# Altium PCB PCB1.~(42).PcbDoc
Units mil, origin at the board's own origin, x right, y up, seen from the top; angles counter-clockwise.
Board outline 6000 x 4000 mil, 2 copper layers (Top Layer, Bottom Layer); 37 components, 28 nets, 157 pads, 81 vias.
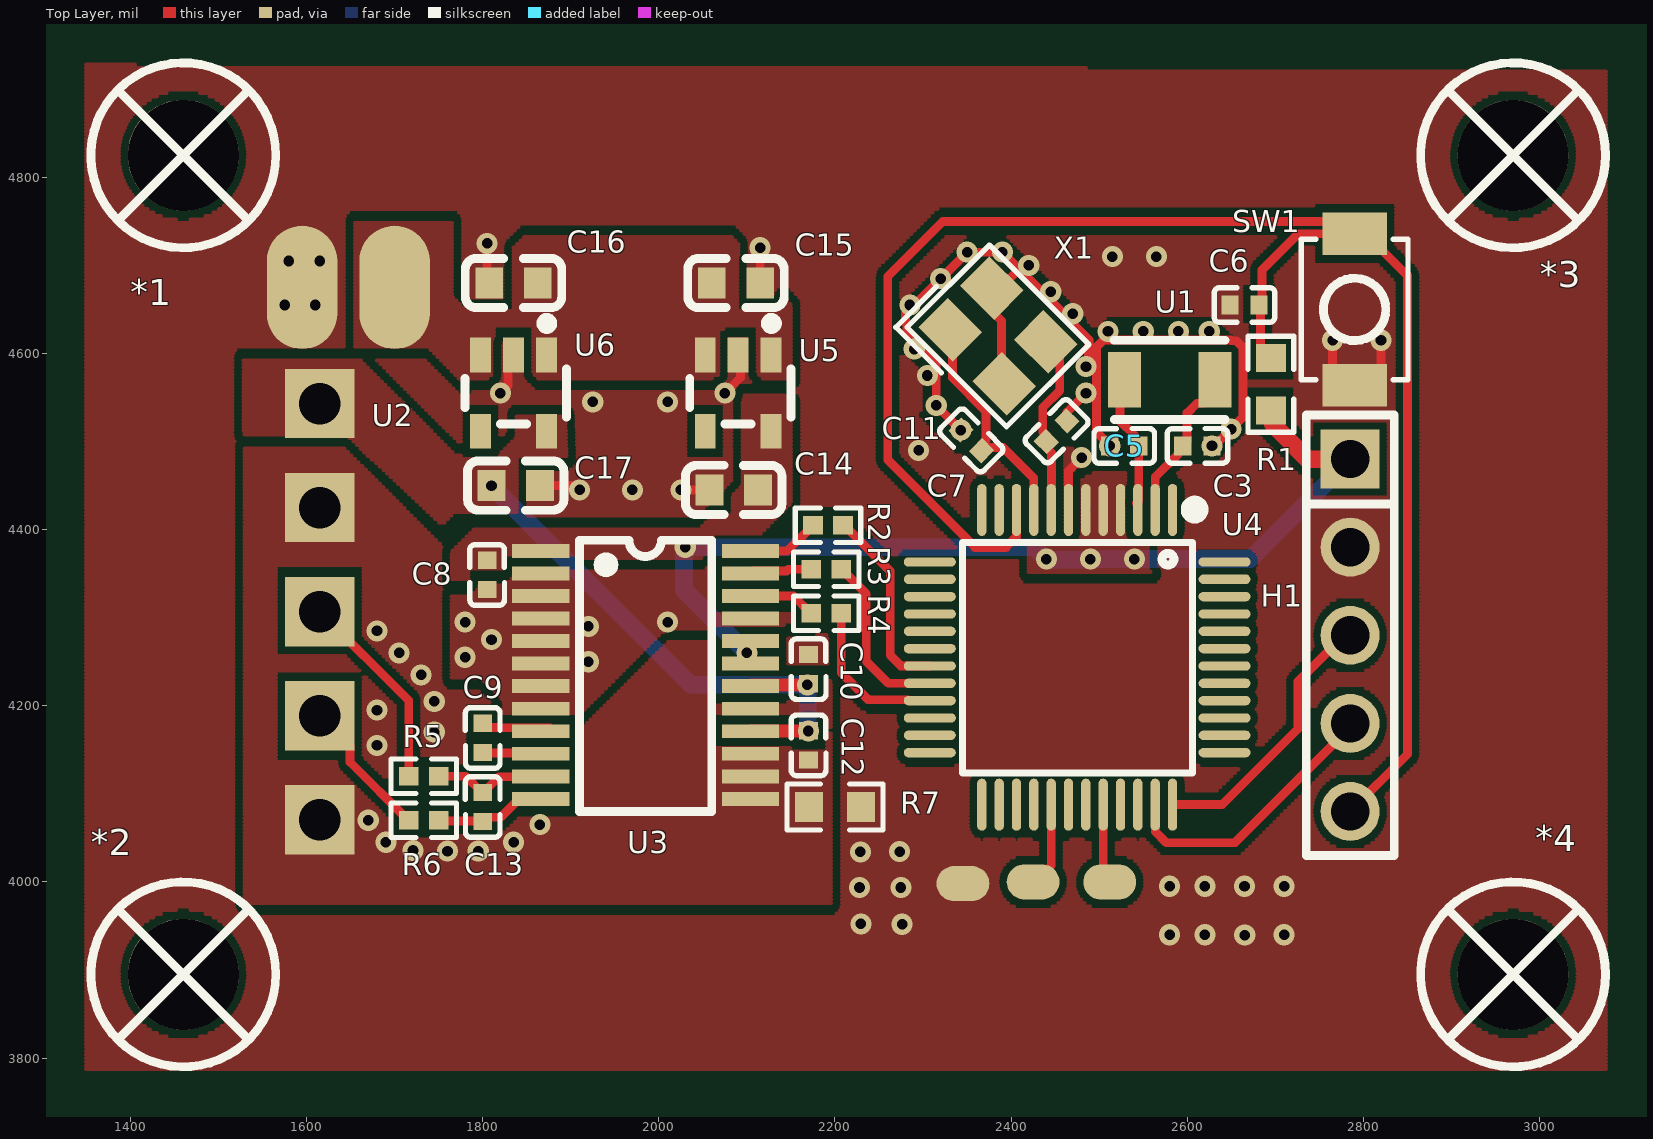
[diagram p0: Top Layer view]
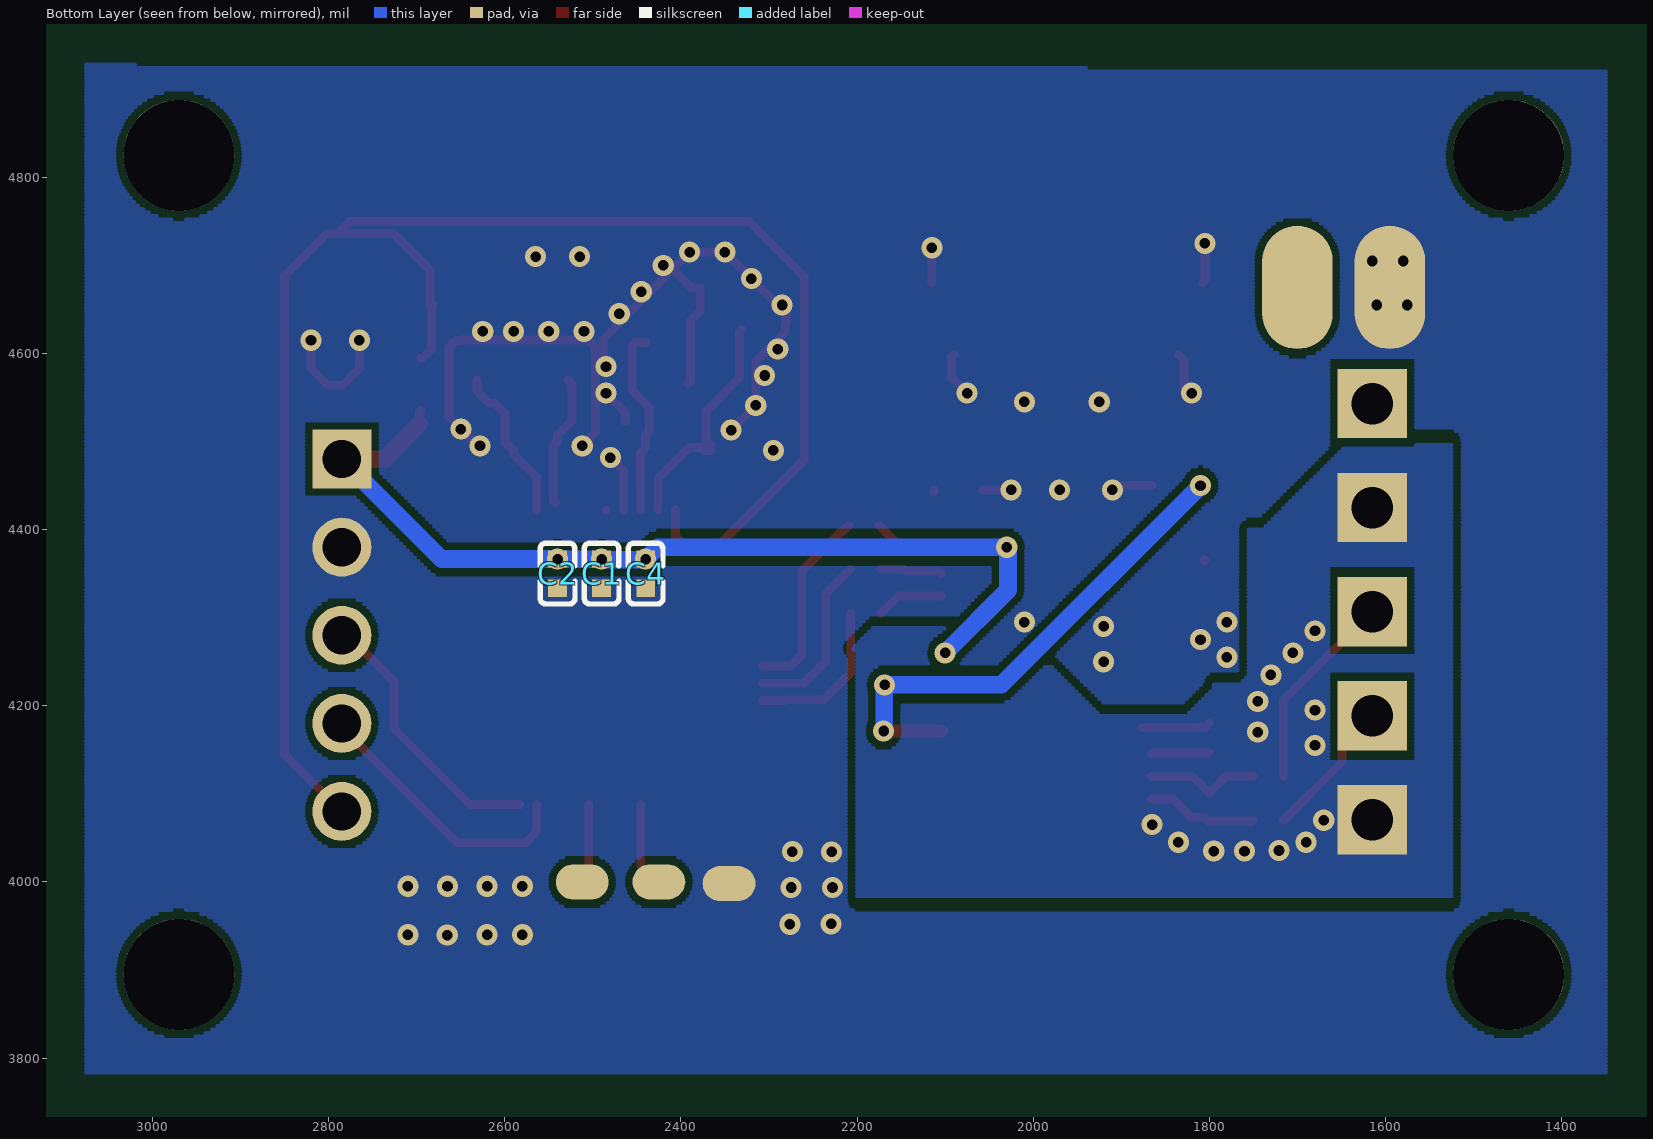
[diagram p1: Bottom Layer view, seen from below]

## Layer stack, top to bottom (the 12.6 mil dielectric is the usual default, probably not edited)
Top Solder: solder mask 0.4, Solder Resist, Dk 3.5
Top Layer: signal copper 1.4
Dielectric 1: dielectric 12.6, FR-4, Dk 4.8
Bottom Layer: signal copper 1.4
Bottom Solder: solder mask 0.4, Solder Resist, Dk 3.5

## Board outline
1000,1000 7000,1000 7000,5000 1000,5000

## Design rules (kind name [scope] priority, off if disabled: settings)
Clearance [All] p1: gap=8 ignorepadtopadclearanceinfootprint=FALSE
ComponentClearance [All] p1: gap=0 collisioncheckmode=3 verticalgap=0 showdistances=FALSE
HoleSize [All] p1: absolutevalues=TRUE maxlimit=130 minlimit=1 maxpercent=80.000 minpercent=20.000
MinimumSolderMaskSliver [All] p1: minsoldermaskwidth=4
PlaneConnect [All] p1: planeconnectstyle=Direct reliefexpansion=20 reliefentries=4 reliefconductorwidth=10 reliefairgap=10
PolygonConnect [All] p1: connectstyle=Direct reliefconductorwidth=10 reliefentries=4 polygonreliefangle="90 Angle" airgapwidth=10
RoutingVias [All] p1: holewidth=28 width=50 viastyle="Through Hole" minholewidth=28 minwidth=50 maxholewidth=28 maxwidth=50
SilkToSilkClearance [All] p1: silktosilkclearance=2
SilkToSolderMaskClearance [IsPad] p1: minsilkscreentomaskgap=2 clearancetoexposedcopper=TRUE
SolderMaskExpansion [All] p1: expansion=0 istentingtop=FALSE
SupplyNets "Schematic Supply Nets_2" [InNet('6V')] p1: voltage=0.000
SupplyNets "Schematic Supply Nets" [InNet('3V3')] p2: voltage=0.000
SupplyNets "Schematic Supply Nets_4" [InNet('5V')] p3: voltage=0.000
SupplyNets "Schematic Supply Nets_3" [InNet('DGND')] p4: voltage=0.000
SupplyNets "Schematic Supply Nets_1" [InNet('AGND')] p5: voltage=0.000
Width [All] p1: maxlimit=50 minlimit=10 preferedwidth=10
24 further rules are at their usual default settings.

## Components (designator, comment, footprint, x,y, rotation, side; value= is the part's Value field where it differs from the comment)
*1 "螺丝孔_1" M3螺丝 1460,4825 r0 top
*2 "螺丝孔_1" M3螺丝 1460,3895 r0 top
*3 "螺丝孔_1" M3螺丝 2970,4825 r0 top
*4 "螺丝孔_1" M3螺丝 2970,3895 r0 top
C1 "cc0402krx7r7bb104" C0402 2490,4350 r90 bottom value=100nF
C2 "cc0402krx7r7bb104" C0402 2540,4350 r270 bottom value=100nF
C3 "cc0402jrnpo9bn220" C0402 2611.54,4495 r180 top value=22pF
C4 "cc0402krx7r7bb104" C0402 2440,4350 r270 bottom value=100nF
C5 "cc0402jrnpo9bn220" C0402 2528.46,4495 r0 top value=22pF
C6 "cc0402krx7r7bb104" C0402 2665,4655 r0 top value=100nF
C7 "cc0402jrnpo9bn180" C0402 2451.7,4511.7 r45 top value=18pF
C8 "cc0402krx7r7bb104" C0402 1805,4348.46 r270 top value=100nF
C9 "cc0402krx7r7bb104" C0402 1800,4163.46 r90 top value=100nF
C10 "cc0402krx7r7bb104" C0402 2170,4241.54 r90 top value=100nF
C11 "cc0402jrnpo9bn180" C0402 2354.68,4501.29 r315 top value=18pF
C12 "gcm155r71h103ka55d" C0402 2170,4155 r270 top value=10nF
C13 "gcm155r71h103ka55d" C0402 1800,4085 r270 top value=10nF
C14 "cga0603x5r105k500jt" C0603 2085,4445 r180 top value=1uF
C15 "cga0603x5r105k500jt" C0603 2087.56,4680 r0 top value=1uF
C16 "cga0603x5r105k500jt" C0603 1835,4680 r180 top value=1uF
C17 "cga0603x5r105k500jt" C0603 1837.44,4450 r0 top value=1uF
H1 "pz254v-11-05p" HDR-TH_5P-P2.54-V-M 2785,4280 r270 top
R1 "frc0603f1002ts" R0603 2695,4565 r270 top value=10kΩ
R2 "frc0402f47r0ts" R0402 2192.04,4405 r0 top value=47Ω
R3 "frc0402f47r0ts" R0402 2190,4355 r0 top value=47Ω
R4 "frc0402f47r0ts" R0402 2190,4305 r0 top value=47Ω
R5 "frc0402f1000ts" R0402 1732.96,4120 r0 top value=100Ω
R6 "frc0402f1000ts" R0402 1732.96,4070 r0 top value=100Ω
R7 "0603waf0000t5e" R0603 2200,4085 r0 top value=0Ω
SW1 "ts-1088-ar02016" SW-SMD_L3.9-W3.0-P4.45 2790,4650 r90 top
U1 "fc31m2-32.768-ntlnndtl" CRYSTAL-SMD_L3.2-W1.5 2580,4570 r0 top value=32.768kHz
U2 "5个焊盘" 5个焊盘 1615,4543.1 r270 top
U3 "ads1232ipwr" TSSOP-24_L7.8-W4.4-P0.65-LS6.4-BL 1985,4235 r270 top
U4 "stm32g031c8t6" LQFP-48_L7.0-W7.0-P0.50-LS9.0-BL 2475,4255 r180 top
U5 "tps7a2033pdbvr" SOT-23-5_L2.9-W1.6-P0.95-LS2.8-BR 2090,4555 r90 top
U6 "tps7a2050pdbvr" SOT-23-5_L2.9-W1.6-P0.95-LS2.8-BR 1835,4555 r90 top
X1 "x32258mob4si" CRYSTAL-SMD_4P-L3.2-W2.5-BL 2385,4620 r315 top value=8MHz

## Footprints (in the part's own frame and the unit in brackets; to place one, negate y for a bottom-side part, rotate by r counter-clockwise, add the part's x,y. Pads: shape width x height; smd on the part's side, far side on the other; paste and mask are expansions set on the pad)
5个焊盘 [mm]
  rect 2x2 hole 1.2: 1(0,0) 2(3,0) 3(6.001,0) 4(9,0) 5(12,0)
C0402 [mm]
  rect 0.5x0.54 smd: 1(-0.42,0) 2(0.42,0)
  silkscreen extent -0.87,-0.5 0.87,0.5
C0603 [mm]
  rect 0.8x0.9 smd: 1(-0.7,0) 2(0.7,0)
  silkscreen extent -1.39,-0.71 1.39,0.71
CRYSTAL-SMD_4P-L3.2-W2.5-BL [mm]
  rect 1.4x1.2 smd: 1(-1.1,-0.85) 2(1.1,-0.85) 3(1.1,0.85) 4(-1.1,0.85)
  silkscreen extent -2.26,-1.91 2.03,1.68
CRYSTAL-SMD_L3.2-W1.5 [mm]
  rect 0.95x1.6 smd: 1(-1.308,0) 2(1.308,0)
  silkscreen extent -1.6,-1.14 1.6,1.14
HDR-TH_5P-P2.54-V-M [mm]
  rect 1.7x1.7 hole 1.1: 1(-5.08,0)
  round 1.7 hole 1.1: 2(-2.54,0) 3(0,0) 4(2.54,0) 5(5.08,0)
  silkscreen extent -6.35,-1.27 6.35,1.27
LQFP-48_L7.0-W7.0-P0.50-LS9.0-BL [mm]
  oval 0.27x1.5 smd paste+0 mask+0.05: 1(-2.75,-4.25) 2(-2.25,-4.25) 3(-1.75,-4.25) 4(-1.25,-4.25) 5(-0.75,-4.25) 6(-0.25,-4.25) 7(0.25,-4.25) 8(0.75,-4.25) 9(1.25,-4.25) 10(1.75,-4.25) 11(2.25,-4.25) 12(2.75,-4.25) 25(2.75,4.25) 26(2.25,4.25) 27(1.75,4.25) 28(1.25,4.25) 29(0.75,4.25) 30(0.25,4.25) 31(-0.25,4.25) 32(-0.75,4.25) 33(-1.25,4.25) 34(-1.75,4.25) 35(-2.25,4.25) 36(-2.75,4.25)
  oval 1.5x0.27 smd paste+0 mask+0.05: 13(4.25,-2.75) 14(4.25,-2.25) 15(4.25,-1.75) 16(4.25,-1.25) 17(4.25,-0.75) 18(4.25,-0.25) 19(4.25,0.25) 20(4.25,0.75) 21(4.25,1.25) 22(4.25,1.75) 23(4.25,2.25) 24(4.25,2.75) 37(-4.25,2.75) 38(-4.25,2.25) 39(-4.25,1.75) 40(-4.25,1.25) 41(-4.25,0.75) 42(-4.25,0.25) 43(-4.25,-0.25) 44(-4.25,-0.75) 45(-4.25,-1.25) 46(-4.25,-1.75) 47(-4.25,-2.25) 48(-4.25,-2.75)
  silkscreen extent -3.59,-4.46 3.3,3.34
M3螺丝 [mil]
  round 126 hole 126 paste-99999 mask+4: 1(0,0)
  silkscreen extent -105,-105 105,105
R0402 [mm]
  rect 0.566x0.54 smd paste-100 mask+0.051: 1(-0.433,0) 2(0.433,0)
  silkscreen extent -0.94,-0.5 0.94,0.5
R0603 [mil]
  rect 31.75x34.02 smd paste-3937.01 mask+2: 1(-29.66,0) 2(29.66,0)
  silkscreen extent -55,-26 55,26
SOT-23-5_L2.9-W1.6-P0.95-LS2.8-BR [mm]
  rect 1x0.6 smd paste+0 mask+0.05: 1(1.1,-0.95) 2(1.1,0) 3(1.1,0.95) 4(-1.1,0.95) 5(-1.1,-0.95)
  silkscreen extent -0.89,-1.52 2.16,1.4
SW-SMD_L3.9-W3.0-P4.45 [mm]
  rect 1.23x1.86 smd: 1(-2.185,0) 2(2.185,0)
  silkscreen extent -2.03,-1.54 2.03,1.54
TSSOP-24_L7.8-W4.4-P0.65-LS6.4-BL [mm]
  rect 0.4x1.65 smd: 1(-3.575,-3.023) 2(-2.925,-3.023) 3(-2.275,-3.023) 4(-1.625,-3.023) 5(-0.975,-3.023) 6(-0.325,-3.023) 7(0.325,-3.023) 8(0.975,-3.023) 9(1.625,-3.023) 10(2.275,-3.023) 11(2.925,-3.023) 12(3.575,-3.023) 13(3.575,3.023) 14(2.925,3.023) 15(2.275,3.023) 16(1.625,3.023) 17(0.975,3.023) 18(0.325,3.023) 19(-0.325,3.023) 20(-0.975,3.023) 21(-1.625,3.023) 22(-2.275,3.023) 23(-2.925,3.023) 24(-3.575,3.023)
  silkscreen extent -3.89,-1.91 3.94,1.91

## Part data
C1 C2 C4 C6 C8 C9 C10: "容值:100nF;精度:±10%;额定电压:16V;温度系数:X7R;", JLCPCB Part Class="Extended Part", LCSC Part Name="100nF ±10% 16V", Manufacturer=YAGEO(国巨), ManufacturerPart=CC0402KRX7R7BB104, Temperature Coefficient=X7R, Tolerance=±10%, Voltage Rating=16V
C3 C5: "容值:22pF;精度:±5%;额定电压:50V;温度系数:NP0;", JLCPCB Part Class="Extended Part", LCSC Part Name="22pF ±5% 50V", Manufacturer=YAGEO(国巨), ManufacturerPart=CC0402JRNPO9BN220, Temperature Coefficient=NP0, Tolerance=±5%, Voltage Rating=50V
C7 C11: "容值:18pF;精度:±5%;额定电压:50V;温度系数:NP0;", JLCPCB Part Class="Extended Part", LCSC Part Name="18pF ±5% 50V", Manufacturer=YAGEO(国巨), ManufacturerPart=CC0402JRNPO9BN180, Temperature Coefficient=NP0, Tolerance=±5%, Voltage Rating=50V
C12 C13: "容值:10nF;精度:±10%;额定电压:50V;温度系数:X7R;", JLCPCB Part Class="Extended Part", LCSC Part Name="10nF ±10% 50V", Manufacturer=muRata(村田), ManufacturerPart=GCM155R71H103KA55D, Temperature Coefficient=X7R, Tolerance=±10%, Voltage Rating=50V
C14 C15 C16 C17: "容值:1uF;精度:±10%;额定电压:50V;温度系数:X5R;", JLCPCB Part Class="Extended Part", LCSC Part Name="1uF ±10% 50V 停产", Manufacturer=HRE(芯声), ManufacturerPart=CGA0603X5R105K500JT, Temperature Coefficient=X5R, Tolerance=±10%, Voltage Rating=50V
H1: "插针结构:1x5P;间距:2.54mm;行距:-;圆针/方针:方针;安装方式:直插;排数:单排;总PIN位数:5P;额定电流:3A;额定电压:250V;配合针长度:6mm;塑高:2.5mm;端接针长度:3mm;触头材质:黄铜;触头镀层:-;工作温度:-40℃~+105℃;颜色:黑色;", Color=黑色, Current Rating=3A, JLCPCB Part Class="Extended Part", LCSC Part Name="1x5P 间距:2.54mm 方针 直插", Manufacturer=XFCN(兴飞), ManufacturerPart=PZ254V-11-05P, Operating Temperature=-40℃~+105℃, Voltage Rating (Max)=250V
R1: "电阻类型:厚膜电阻;阻值:10kΩ;精度:±1%;功率:100mW;工作电压:75V;温度系数:±100ppm/℃;", JLCPCB Part Class="Extended Part", LCSC Part Name="10kΩ ±1% 100mW 厚膜电阻", Manufacturer=FOJAN(富捷), ManufacturerPart=FRC0603F1002TS, Operating Temperature=-55℃~+155℃, Power(Watts)=100mW, Temperature Coefficient=±100ppm/℃, Tolerance=±1%, Voltage-Supply(Max)=75V
R2 R3 R4: "电阻类型:厚膜电阻;阻值:47Ω;精度:±1%;功率:62.5mW;工作电压:50V;温度系数:±100ppm/℃;", JLCPCB Part Class="Extended Part", LCSC Part Name="47Ω ±1% 62.5mW 厚膜电阻", Manufacturer=FOJAN(富捷), ManufacturerPart=FRC0402F47R0TS, Operating Temperature=-55℃~+155℃, Power(Watts)=62.5mW, Temperature Coefficient=±100ppm/℃, Tolerance=±1%, Voltage-Supply(Max)=50V
R5 R6: "电阻类型:厚膜电阻;阻值:100Ω;精度:±1%;功率:62.5mW;工作电压:50V;温度系数:±100ppm/℃;", JLCPCB Part Class="Extended Part", LCSC Part Name="100Ω ±1% 62.5mW 厚膜电阻", Manufacturer=FOJAN(富捷), ManufacturerPart=FRC0402F1000TS, Operating Temperature=-55℃~+155℃, Power(Watts)=62.5mW, Temperature Coefficient=±100ppm/℃, Tolerance=±1%, Voltage-Supply(Max)=50V
R7: "电阻类型:厚膜电阻;阻值:0Ω;精度:±1%;功率:100mW;工作电压:75V;温度系数:-;", JLCPCB Part Class="Basic Part", LCSC Part Name="0Ω ±1% 100mW 厚膜电阻", Manufacturer=UNI-ROYAL(厚声), ManufacturerPart=0603WAF0000T5E, Operating Temperature=-55℃~+155℃, Power(Watts)=100mW, Temperature Coefficient=-, Tolerance=±1%, Voltage-Supply(Max)=75V
SW1: "电路结构:单刀单掷;按钮形状:圆形按钮;作用力:1.6N;安装方式:立贴;开关长度:3.9mm;开关宽度:3mm;开关高度:2mm;带支架:不带支架;触点电流:50mA;额定电压:12V;带灯:-;工作寿命:10万次;", Actuator/Cap Color=黑色, Contact Current=50mA, IP Rating=-, JLCPCB Part Class="Basic Part", LCSC Part Name="3.9*3*2mm 立贴 轻触开关", Manufacturer=XUNPU(讯普), ManufacturerPart=TS-1088-AR02016, Operating Force=1.6N, Operating Temperature=-30℃~+80℃, Voltage Rating=12V
U1: "晶振类型:贴片晶振;频率:32.768kHz;常温频差:±10ppm;负载电容:12.5pF;频率稳定度:±10ppm;", Equivalent Series Resistance(ESR)=70kΩ, Frequency Stability=±10ppm, JLCPCB Part Class="Extended Part", LCSC Part Name="3215 2P 32.768kHz 12.5pF ±10ppm -40~+85℃(±10ppm)", Load Capacitance=12.5pF, Manufacturer=HCI(杭晶), ManufacturerPart=FC31M2-32.768-NTLNNDTL, Operating Temperature=-40℃~+85℃
U3: "分辨率(位):24;采样率:10Hz;工作电压:2.7V~5.3V;接口类型:SPI;", Clock Frequency=4.9152MHz；200kHz~8MHz, JLCPCB Part Class="Extended Part", LCSC Part Name="用于桥式传感器的24bit 模数转换器", Manufacturer=TI(德州仪器), ManufacturerPart=ADS1232IPWR, Operating Temperature=-40℃~+105℃, Quiescent Current (Iq)=1.3uA, Temperature Sensors=内置, Voltage - Supply=2.7V~5.3V, Voltage Reference=外置, Voltage Reference Drift=-
U4: "CPU内核:ARM Cortex-M0+;CPU最大主频:64MHz;CPU位数:32 Bit;", JLCPCB Part Class="Extended Part", LCSC Part Name="主流Arm Cortex-M0+ MCU，具有64 KB Flash存储器、8 KB RAM、64 MHz CPU、2x USART、定时器、ADC和通信接口，1.7-3.6V", Manufacturer=ST(意法半导体), ManufacturerPart=STM32G031C8T6, Operating Temperature=-40℃~+85℃, Voltage - Supply=1.7V~3.6V
U5: "输出类型:固定;最大输入电压:6V;输出电压:3.3V;输出电流:300mA;输出极性:正极;", Dropout Voltage=140mV@(300mA), JLCPCB Part Class="Extended Part", LCSC Part Name="具有高 PSRR 的 300mA、超低噪声、低 IQ、低压降 (LDO) 线性稳压器", Manufacturer=TI(德州仪器), ManufacturerPart=TPS7A2033PDBVR, Maximum Input Voltage=6V, Operating Temperature=-40℃~+125℃@(Tj), Output Current=300mA, Output Voltage=3.3V, standby current=15uA
U6: "输出极性:正极;工作电压:6V;输出电压:5V;输出电流:300mA;电源纹波抑制比(PSRR):65dB@(100Hz);输出类型:固定;", JLCPCB Part Class="Extended Part", LCSC Part Name="800mV~5.5V 300mA 6V", Manufacturer=TI(德州仪器), ManufacturerPart=TPS7A2050PDBVR, Operating Temperature=-40℃~+125℃@(Tj), Output Current=300mA, Output Voltage=5V, Power Supply Rejection Ratio (PSRR)=65dB@(100Hz), standby current=6.5uA, Voltage - Supply=6V, Voltage Dropout=140mV@(300mA)
X1: "晶振类型:贴片晶振;频率:8MHz;常温频差:±10ppm;负载电容:12pF;频率稳定度:±20ppm;", Equivalent Series Resistance(ESR)=180Ω, Frequency Stability=±20ppm, JLCPCB Part Class="Extended Part", LCSC Part Name="YSX321SL 8MHZ 4P 3225 12PF ±10PPM -40~85℃ (±20PPM)", Load Capacitance=12pF, Manufacturer=YXC(扬兴晶振), ManufacturerPart=X32258MOB4SI, Normal temperature Frequency Tolerance=±10ppm, Operating Temperature=-40℃~+85℃

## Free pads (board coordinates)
  oval 80x140 all layers, no hole: 7(1595,4675) 7(1700,4675)
  oval 60x40 all layers, no hole: 7(2345.3,3998) 7(2425,4000) 7(2512,3999.83)

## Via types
v1: diameter 24, hole 12, Top Layer to Bottom Layer, tented both sides, 81 vias

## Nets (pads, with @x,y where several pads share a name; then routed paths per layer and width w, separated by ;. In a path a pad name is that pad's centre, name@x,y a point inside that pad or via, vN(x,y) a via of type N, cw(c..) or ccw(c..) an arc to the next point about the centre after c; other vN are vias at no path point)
3V3: C1.2 C2.1 C4.1 C8.1 C14.1 H1.1 R1.2 U3.1 U3.19 U3.20 U4.4 U4.5 U4.6 U5.5 | length 1084.5
  Top Layer w10: C8.1 C8.1@1805.79,4365 ; C14.1@2112.56,4443.03 C14.1 ; v1(2440,4366.54) v1@2442.68,4369.22 ; U4.6@2484.72,4422.2 U4.6 ; R1.2 2697.01,4533.33 R1.2@2697.01,4519.53
  Top Layer w20: R1.2@2697.01,4519.53 2736.54,4480 H1.1
  Bottom Layer w10: v1@2028.6,4378.6 v1(2030,4380) ; 2058.74,4380 2060.53,4378.21
  Bottom Layer w20: v1@2028.6,4378.6 2028.6,4331.4 v1(2100,4260) ; v1@2030.11,4379.89 2426.18,4379.89 C4.1@2439.37,4366.7 ; C4.1@2440.69,4365.85 C1.2@2489.31,4365.85 ; C1.2@2490.63,4366.49 C2.1@2539.37,4366.49 ; v1(2540,4366.54) 2671.54,4366.54 H1.1
  other v1: 2490,4366.54
5V: C10.1 C12.1 C17.1 U2.1 U3.16 U3.18 U6.5 | length 638.5
  Top Layer w10: U3.16 U3.16@2104.26,4171.28 ; U3.18 U3.18@2105.39,4223.6 ; v1(2168.61,4223.6) C10.1 ; v1(2169.74,4171.28) C12.1
  Top Layer w15: U3.16@2104.26,4171.28 v1(2169.74,4171.28) ; U3.18@2105.39,4223.6 v1(2168.61,4223.6)
  Bottom Layer w10: v1(2168.61,4223.6) v1@2169.17,4223.04 ; v1@2169.17,4171.85 v1(2169.74,4171.28)
  Bottom Layer w20: v1(1810,4450) 2036.39,4223.6 v1(2168.61,4223.6) ; v1@2169.17,4171.85 v1@2169.17,4223.04
6V: C15.1 C16.1 pad.7@1700,4675 U5.1 U5.3 U6.1 U6.3
AGND: C10.2 C12.2 R7.1 U2.2 U2.5 U3.13 U3.14 U3.15 U3.17
  other v1: 1760,4035 1795,4035 1720.87,4035.63 1690,4045 1835,4045 1865,4065 1670,4070 1680,4155 1745,4170 1680,4195 1745,4205 1730,4235 1705,4260 1680,4285
AINN1: R6.1 U2.4 | length 160.9
  Top Layer w10: U2.4 1649.37,4154.39 1649.37,4136.04 1715.41,4070 R6.1
AINP1: R5.1 U2.3 | length 228.7
  Top Layer w10: U2.3 1715.92,4205.94 R5.1
DGND: C1.1 C2.2 C3.1 C4.2 C5.1 C6.1 C7.2 C8.2 C11.1 C14.2 C15.2 C16.2 C17.2 H1.2 pad.7@1595,4675 pad.7@2345.3,3998 R7.2 SW1.1 U3.2 U3.3 U3.4 U3.5 U3.6 U3.7 U3.8 U3.21 U4.7 U5.2 U6.2 X1.2 X1.4 | length 1554.1
  Top Layer w10: v1(1805,4725) 1805,4682.44 C16.2 ; v1(1820,4555) 1828.62,4563.62 1828.62,4591.92 U6.2 ; C17.2 1901.21,4450 1906.21,4445 v1(1910,4445) ; v1(2025,4445) C14.2 ; v1(2075,4555) 2092.68,4572.68 2092.68,4595.63 U5.2 ; v1(2115,4720) 2115.12,4719.88 C15.2 ; v1(2342.98,4512.98) v1(2315,4540.96) 2315,4590.88 2281.52,4624.36 2281.52,4633.48 2280,4635 2280,4645 v1(2350,4715) v1(2390,4715) v1@2409.14,4695.86 ; X1.2 2389.18,4568.5 2389.18,4636.81 2378.04,4647.95 X1.4 2387.57,4674.29 v1@2409.14,4695.86 ; C7.2 2462.83,4523.95 2462.83,4530.8 2463.39,4531.35 2463.39,4533.39 v1(2485,4555) ; U4.7 2465.16,4466.85 v1(2480,4481.69) v1@2480,4485 ; v1(2485,4585) 2487.68,4587.68 2487.68,4604.07 2488.48,4604.87 2488.48,4615.64 2457.06,4647.06 2457.06,4647.94 v1@2409.14,4695.86 ; v1(2511.92,4495) 2511.92,4495.79 2496.8,4510.91 2496.8,4606.88 2505.36,4615.44 2649.41,4615.44 2650.35,4614.5 2655.59,4614.5 2663.2,4606.88 2663.2,4527.61 v1(2649.71,4514.12) 2636.22,4500.63 2632.92,4500.63 C3.1@2628.08,4495.79 ; v1(2765,4615) 2765,4583.19 2784.21,4563.98 SW1.1 2800.79,4563.98 2820,4583.19 v1(2820,4615)
  other v1: 2580,3940 2620,3940 2665.24,3939.54 2710,3940 2229.44,3952.22 2276.16,3951.9 2227.87,3993.61 2274.91,3993.61 2580,3995 2620,3995 2665,3995 2710,3995 2228.81,4034.06 2273.34,4034.38 1920,4250 1780,4255 1810,4275 1920,4290 1780,4295 2010,4295 1970,4445 2295,4490 2628.08,4495 1925,4545 2010,4545 2305,4575 2290,4605 2510,4625 2550,4625 2590,4625 2625,4625 2470,4645 1575,4655 1610,4655 2285,4655 2445,4670 2320,4685 2420,4700 1580,4705 1615,4705 2515,4710 2565,4710
DOUT: R2.2 U4.19 | length 220.8
  Top Layer w10: R2.2 2214.71,4399.37 2216.12,4399.37 2262.67,4352.82 2262.67,4257.23 2274.62,4245.28 2307.56,4245.28 U4.19
NetC3_2: C3.2 U1.2 U4.2 | length 179.8
  Top Layer w10: U4.2 2563.58,4440 2563.58,4459.72 2590.16,4486.3 2590.16,4490.16 2599.84,4499.84 2599.84,4532.3 2611.05,4543.5 2617.8,4543.5 2631.5,4557.21 U1.2
NetC5_2: C5.2 U1.1 U4.3 | length 152
  Top Layer w10: U1.1 2523.5,4565 2523.5,4523.5 2540.16,4506.85 2540.16,4499.84 C5.2 2545,4432.48 U4.3@2542.53,4430
NetC7_1: C7.1 U4.8 X1.3 | length 216.4
  Top Layer w10: X1.3 2440,4612.33 2452.33,4612.33 2455.11,4609.54 2455.11,4557.75 2435.91,4538.56 2435.91,4510.93 2440,4506.85 2440,4493.15 2445.87,4487.28 2445.87,4447.11 2445.59,4446.82 2445.59,4422.89 U4.8@2445.76,4422.72
NetC9_1: C9.1 U3.10 | length 66.6
  Top Layer w10: C9.1 1800.74,4146.18 1865.26,4146.18 U3.10
NetC9_2: C9.2 U3.9 | length 78.3
  Top Layer w10: C9.2 1804.84,4175.16 1819.84,4175.16 1820,4175 U3.9@1876.23,4175
NetC11_2: C11.2 U4.9 X1.1 | length 267.5
  Top Layer w10: X1.1 2333.5,4624.18 2333.5,4572.39 2371.34,4534.54 2371.34,4501.41 2366.37,4496.44 C11.2 2373.22,4489.59 2376.7,4493.07 2391.02,4493.07 2425.67,4458.42 2425.67,4422.44 U4.9
NetC13_1: C13.1 R5.2 U3.11 | length 131.2
  Top Layer w10: R5.2 1780.75,4120 1799.21,4101.54 C13.1 1800.79,4101.54 1818.52,4119.27 1865.43,4119.27 U3.11
NetC13_2: C13.2 R6.2 U3.12 | length 127.3
  Top Layer w10: R6.2 1750.77,4069.23 1799.23,4069.23 C13.2 1804.84,4073.3 1820.44,4073.3 1841.39,4094.26 U3.12
NetR2_1: R2.1 U3.24 | length 83.4
  Top Layer w10: U3.24 2145.74,4375.74 2168.86,4398.86 2168.86,4399.37 2174.49,4405 R2.1
NetR3_1: R3.1 U3.23 | length 71
  Top Layer w10: U3.23 2106.87,4353.02 2144.85,4353.02 2146.82,4355 R3.1
NetR4_1: R4.1 U3.22 | length 77.1
  Top Layer w10: U3.22 2152.89,4324.56 2172.45,4305 R4.1
NRST: C6.2 H1.5 R1.1 SW1.2 U4.10 | length 1937.5
  Top Layer w10: U4.10 2405.98,4422.2 2405.98,4391.77 2394.01,4379.79 2359.14,4379.79 2259.83,4479.1 2259.83,4687.33 2322.36,4749.85 2776.17,4749.85 SW1.2 ; C6.2 C6.2@2681.54,4655.79 ; R1.1 2693.87,4594.66 2682.99,4605.54 2682.99,4652.99 2685,4655 2685,4695 2726.02,4736.02 SW1.2 ; H1.5 2850,4145 2850,4688.42 2802.4,4736.02 SW1.2
PDWN: R4.2 U4.21 | length 181.3
  Top Layer w10: R4.2 2207.04,4237.44 2237.61,4206.87 2282.22,4206.87 2283.3,4205.79 U4.21
SCLK: R3.2 U4.20 | length 199
  Top Layer w10: R3.2 2207.55,4355 2235.58,4326.97 2235.58,4250.61 2260.6,4225.59 2307.56,4225.59 U4.20
SWCLK: H1.3 U4.36 | length 312.7
  Top Layer w10: U4.36 2639.37,4087.68 2725.86,4174.17 2725.86,4227.64 2778.22,4280 H1.3
SWDIO: H1.4 U4.35 | length 315.9
  Top Layer w10: U4.35 2563.7,4087.56 2563.7,4057.14 2576.32,4044.52 2654.07,4044.52 2785,4175.45 H1.4
USART1_RX: pad.7@2512,3999.83 U4.32 | length 90.9
  Top Layer w10: U4.32 2504.65,4087.56 2504.65,4007.18 pad.7@2512,3999.83
USART1_TX: pad.7@2425,4000 U4.29 | length 97.3
  Top Layer w10: pad.7@2425,4000 2426.88,4000 2445.47,4018.59 U4.29
USART2_RX: U4.14
USART2_TX: U4.13
pads on no net: *1.1 *2.1 *3.1 *4.1 U4.1 U4.11 U4.12 U4.15 U4.16 U4.17 U4.18 U4.22 U4.23 U4.24 U4.25 U4.26 U4.27 U4.28 U4.30 U4.31 U4.33 U4.34 U4.37 U4.38 U4.39 U4.40 U4.41 U4.42 U4.43 U4.44 U4.45 U4.46 U4.47 U4.48 U5.4 U6.4

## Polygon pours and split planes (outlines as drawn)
DGND on Top Layer "NONET_L-01_P-001" (hatched Horizontal grid 4 track 5, remove dead copper, pour order 15): 1350,4928.2 1350,3785 3075,3785 3075,4921.81
5V on Top Layer "NONET_L-01_P-001" (hatched Horizontal grid 4 track 5, remove dead copper, pour order 9): 1893.57,4530 1873.57,4530 1838.57,4530 1838.57,4505 1818.57,4485 1768.57,4485 1658.57,4595 1528.57,4595 1528.57,4505 1645,4505 1680,4475 1753.57,4405 1768.57,4420 1838.57,4420 1838.57,4480 1843.57,4485 1848.57,4480 1895,4480
3V3 on Top Layer "NONET_L-01_P-001" (hatched Horizontal grid 4 track 5, remove dead copper, pour order 8): 2420,4385 2420,4350 2560,4350 2555,4355 2555,4385 2545,4385 2535,4395 2535,4465 2475,4465 2475,4390 2425,4390
AGND on Top Layer "NONET_L-01_P-001" (hatched Horizontal grid 4 track 5, remove dead copper, pour order 7): 1565,4495 1640,4495 1755,4380 1755,4225 1795,4225 1827.5,4192.5 1907.5,4192.5 1915,4185 2010,4280 2180,4280 2185,4285 2195,4275 2195,3975 2180,3975 2160,3975 1530,3975 1530,4495
DGND on Top Layer "NONET_L-01_P-001" (hatched Horizontal grid 4 track 5, remove dead copper, pour order 5): 1765,4340 1820,4340 1832.5,4352.5 1830,4355 1830,4365 1905,4365 1960,4310 2135,4310 2135,4290 2130,4285 2005,4285 1905,4185 1830,4185 1830,4200 1800,4230 1765,4230
6V on Top Layer "NONET_L-01_P-001" (hatched Horizontal grid 4 track 5, remove dead copper, pour order 3): 1655,4750 1655,4605 1740,4605 1780,4565 1785,4570 1810,4570 1810,4615 1820,4625 1855,4625 1855,4580 1865,4570 2070,4570 2070,4625 2075,4630 2105,4630 2105,4585 2120,4570 2150,4570 2150,4655 2140,4665 2090,4665 2090,4725 2080,4735 1850,4735 1835,4720 1835,4650 1780,4650 1765,4665 1765,4750
3V3 on Top Layer "NONET_L-01_P-001" (hatched Horizontal grid 4 track 5, remove dead copper, pour order 2): 2095,4555 2095,4450 2045,4400 1790,4400 1765,4375 1765,4340 1820,4340 1845,4365 2045,4365 2070,4390 2110,4390 2150,4430 2150,4545 2140,4555
DGND on Bottom Layer "NONET_L-01_P-001" (hatched Horizontal grid 4 track 5, remove dead copper, pour order 16): 3075,4928.2 3075,3780 1350,3780 1350,4921.81
AGND on Bottom Layer "NONET_L-01_P-001" (hatched Horizontal grid 4 track 5, remove dead copper, pour order 12): 1525,4500 1640,4500 1740,4400 1755,4400 1755,4235 1765,4225 1795,4225 1795,4220 1825,4190 1925,4190 2025,4290 2180,4290 2205,4265 2200,4260 2200,3980 1525,3980

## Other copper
Top Layer:
  pour cut-out: 2275,4655 2350,4730 2350,4735 2390,4735 2485,4640 2485,4635 2495,4625 2510,4640 2630.08,4640 2665,4605.08 2665,4510 2630,4475 2490,4475 2445,4520 2415,4490 2335,4490 2295,4530 2300,4535 2300,4580 2265,4615 2270,4620 2270,4660

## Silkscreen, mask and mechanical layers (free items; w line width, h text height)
Mechanical 1:
  lines w10: 1345,3775 3085,3775 3085,4930 1345,4930 1345,3775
